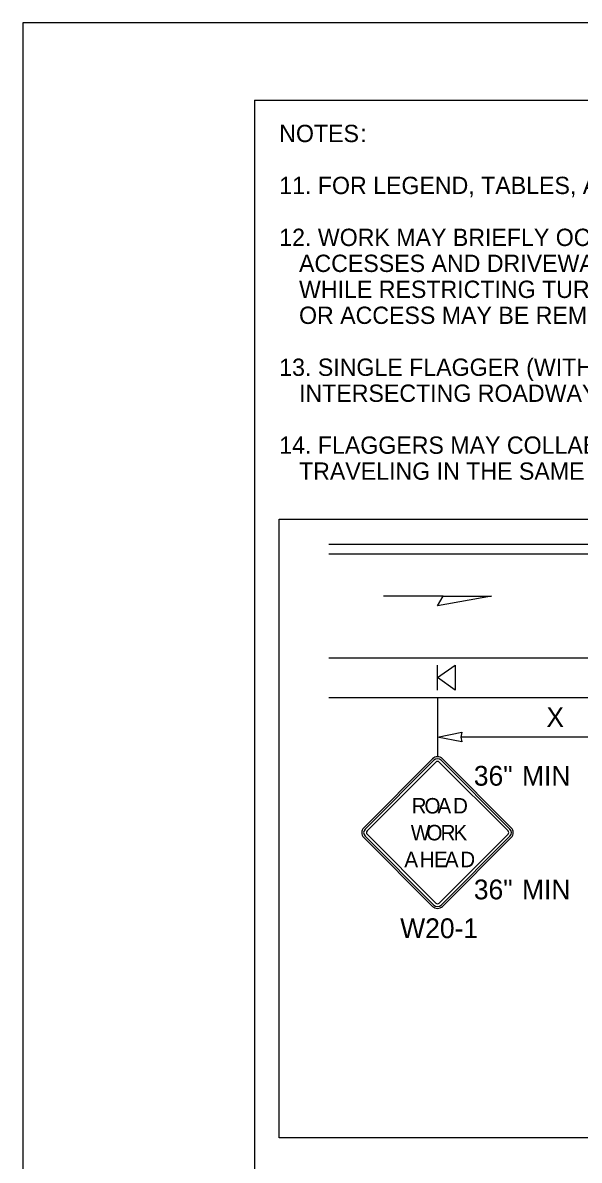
# Model space of a CAD drawing. Extents: x 99999.1 to 100095.7, y 99995 to 100010.7.
# Drawn here: x 100059.062 to 100061.313, y 100006.089 to 100010.687 of the extents above; entities that cross this region are included whole.
import ezdxf

# ---------------------------------------------------------------- set-up
doc = ezdxf.new("R2010")
doc.units = 0
for name, color, linetype in [('RD_ED_ShoulderPavedEdge', 7, 'Continuous'), ('RD_MK_LineDblYellowCenter', 7, 'Continuous'), ('RD_MK_LineEdgeWhite', 7, 'Continuous'), ('SH_GI_GeneralNotesBodyText', 7, 'Continuous'), ('SH_GI_PlotLimits', 7, 'Continuous'), ('SH_GI_SheetBorder', 7, 'Continuous'), ('TR_SN_ConstructionSigns', 7, 'Continuous'), ('TR_WZ_PortableSignMountBlk-Org', 7, 'Continuous'), ('TR_WZ_WorkZoneDetails', 7, 'Continuous'), ('TR_WZ_WorkZoneTextCurrent', 7, 'Continuous')]:
    doc.layers.add(name, color=color, linetype=linetype)

msp = doc.modelspace()

# ---------------------------------------------------------------- linework, layer by layer
at = {"layer": 'RD_ED_ShoulderPavedEdge'}
msp.add_line((100060.3, 100007.9602), (100064.9804, 100007.9602), dxfattribs=at)
at = {"layer": 'RD_MK_LineDblYellowCenter'}
for p, q in [((100060.3, 100008.5802), (100063.7402, 100008.5802)), ((100060.3, 100008.5402), (100063.7402, 100008.5402))]:
    msp.add_line(p, q, dxfattribs=at)
at = {"layer": 'RD_MK_LineEdgeWhite'}
msp.add_line((100060.3, 100008.1202), (100064.9804, 100008.1202), dxfattribs=at)
at = {"layer": 'SH_GI_PlotLimits'}
msp.add_lwpolyline([(100059.0625, 99999.6875), (100076.0625, 99999.6875), (100076.0625, 100010.6875), (100059.0625, 100010.6875)], close=True, dxfattribs=at)
at = {"layer": 'SH_GI_SheetBorder'}
for q in [(100060, 100000), (100075.75, 100010.375)]:
    msp.add_line((100060, 100010.375), q, dxfattribs=at)
at = {"layer": 'TR_SN_ConstructionSigns'}
for p, q in [((100060.7203, 100007.712), (100060.4419, 100007.4336)), ((100060.7258, 100007.7065), (100060.4474, 100007.428)), ((100060.4551, 100007.4203), (100060.7335, 100007.6987)), ((100060.7468, 100007.6987), (100061.0252, 100007.4203)), ((100061.0329, 100007.428), (100060.7545, 100007.7065)), ((100061.0385, 100007.4336), (100060.76, 100007.712)), ((100060.4474, 100007.3993), (100060.7258, 100007.1209)), ((100060.7335, 100007.1286), (100060.4551, 100007.4071)), ((100061.0252, 100007.4071), (100060.7468, 100007.1286)), ((100060.7545, 100007.1209), (100061.0329, 100007.3993)), ((100060.4419, 100007.3938), (100060.7203, 100007.1154)), ((100060.76, 100007.1154), (100061.0385, 100007.3938))]:
    msp.add_line(p, q, dxfattribs=at)
for centre, radius, start, end in [((100060.7402, 100007.6921), 0.0281, 45, 135), ((100060.7402, 100007.6921), 0.0203, 45, 135), ((100060.7402, 100007.6921), 0.00937, 45, 135), ((100060.4617, 100007.4137), 0.0281, 135, 225), ((100060.4617, 100007.4137), 0.0203, 135, 225), ((100060.4617, 100007.4137), 0.00937, 135, 225), ((100061.0186, 100007.4137), 0.00937, 315, 45), ((100061.0186, 100007.4137), 0.0203, 315, 45), ((100061.0186, 100007.4137), 0.0281, 315, 45), ((100060.7402, 100007.1353), 0.0203, 225, 315), ((100060.7402, 100007.1353), 0.00937, 225, 315), ((100060.7402, 100007.1353), 0.0281, 225, 315)]:
    msp.add_arc(centre, radius, start, end, dxfattribs=at)
at = {"layer": 'TR_WZ_PortableSignMountBlk-Org'}
msp.add_line((100060.7402, 100007.9902), (100060.7402, 100008.0902), dxfattribs=at)
msp.add_lwpolyline([(100060.7402, 100008.0401), (100060.812, 100008.0902), (100060.812, 100007.9902)], close=True, dxfattribs=at)
at = {"layer": 'TR_WZ_WorkZoneDetails'}
for p, q in [((100060.7624, 100008.3695), (100060.5213, 100008.3695)), ((100060.7402, 100007.9605), (100060.7402, 100007.7202)), ((100061.5964, 100007.8002), (100060.8339, 100007.8002))]:
    msp.add_line(p, q, dxfattribs=at)
for points in [[(100060.959, 100008.3695), (100060.7402, 100008.3309), (100060.7624, 100008.3695)], [(100060.7402, 100007.8002), (100060.8384, 100007.8195), (100060.8339, 100007.8002), (100060.8384, 100007.781)]]:
    msp.add_lwpolyline(points, close=True, dxfattribs=at)
at = {"layer": 'TR_WZ_WorkZoneTextCurrent'}
msp.add_lwpolyline([(100060.1, 100008.6802), (100065.15, 100008.6802), (100065.15, 100006.1804), (100060.1, 100006.1804)], close=True, dxfattribs=at)

# ---------------------------------------------------------------- texts
at = {"layer": 'SH_GI_GeneralNotesBodyText'}
for s, p in [('NOTES', (100060.1, 100010.205)), (':', (100060.4275, 100010.205)), ('11. FOR LEGEND, TABLES, AND ADDITIONAL NOTES: SEE TC322, SHEET 3.', (100060.1, 100009.995)), ('12. WORK MAY BRIEFLY OCCUR WITHIN LANE CLOSURE ACROSS INTERSECTING BUSINESS ', (100060.1, 100009.785)), ('ACCESSES AND DRIVEWAYS ONLY. ', (100060.18, 100009.68)), ('WHILE RESTRICTING TURNS FROM MAINLINE. CHANNELIZATION DEVICES DELINEATING APPROACH ', (100060.18, 100009.575)), ('OR ACCESS MAY BE REMOVED OR RELOCATED AS NEEDED.', (100060.18, 100009.47)), ('13. SINGLE FLAGGER (WITH RED FLAG/ RED GLOW CONE FLASHLIGHT) MAY BE ADDED TO THE ', (100060.1, 100009.26)), ('INTERSECTING ROADWAY APPROACH TO HELP GUIDE ALTERNATING & TURNING TRAFFIC.', (100060.18, 100009.155)), ('14. FLAGGERS MAY COLLABORATE TO RELEASE APPROACH/ACCESS AND MAINLINE TRAFFIC ', (100060.1, 100008.945)), ('TRAVELING IN THE SAME DIRECTION CONCURRENTLY.', (100060.18, 100008.84))]:
    msp.add_text(s, height=0.07, rotation=360, dxfattribs=at).set_placement(p)
at = {"layer": 'TR_SN_ConstructionSigns'}
for s, p in [('36"', (100060.8869, 100007.6035)), ('MIN', (100061.0819, 100007.6035)), ('36"', (100060.8869, 100007.1439)), ('MIN', (100061.0819, 100007.1439)), ('W20-1', (100060.5892, 100006.9871))]:
    msp.add_text(s, height=0.08, rotation=360, dxfattribs=at).set_placement(p)
for s, p in [('R', (100060.6351, 100007.491)), ('O', (100060.6872, 100007.491)), ('A', (100060.74, 100007.491)), ('D', (100060.8027, 100007.491)), ('W', (100060.6318, 100007.3824)), ('O', (100060.6951, 100007.3824)), ('R', (100060.7523, 100007.3824)), ('K', (100060.8047, 100007.3824)), ('A', (100060.6058, 100007.2739)), ('H', (100060.6683, 100007.2739)), ('E', (100060.7258, 100007.2739)), ('A', (100060.7695, 100007.2739)), ('D', (100060.832, 100007.2739))]:
    msp.add_text(s, height=0.0625, dxfattribs=at).set_placement(p)
at = {"layer": 'TR_WZ_WorkZoneTextCurrent'}
msp.add_text('X', height=0.08, rotation=360, dxfattribs=at).set_placement((100061.1804, 100007.8402))

doc.saveas('drawing.dxf')
